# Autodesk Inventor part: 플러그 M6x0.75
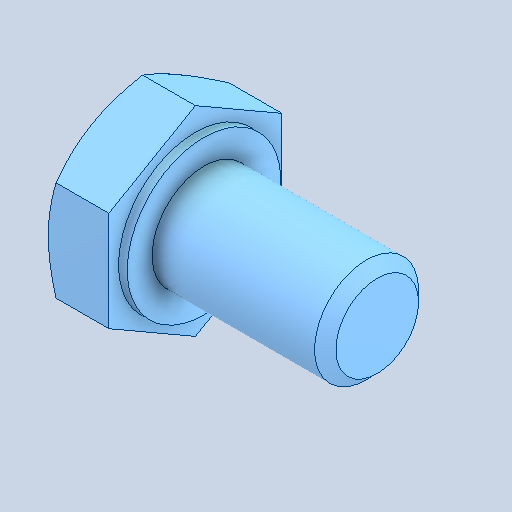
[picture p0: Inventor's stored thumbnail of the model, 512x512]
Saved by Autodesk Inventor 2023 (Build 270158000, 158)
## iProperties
Created: 2026-03
Part Number: 플러그 M6x0.75
Material: 강철, 연강
Description: 6각 머리 볼트 및 6각 머리 나사
Document SubType Name: Modeling
Designer: 4강의실
Density: 7.85 g/cm^3
Appearance: 기본값
Author: jhkim
Sending System: Autodesk Inventor 2026
Preprocessor: ST-DEVELOPER v20.1
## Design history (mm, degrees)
feature "Solid1"
node "솔리드1"
